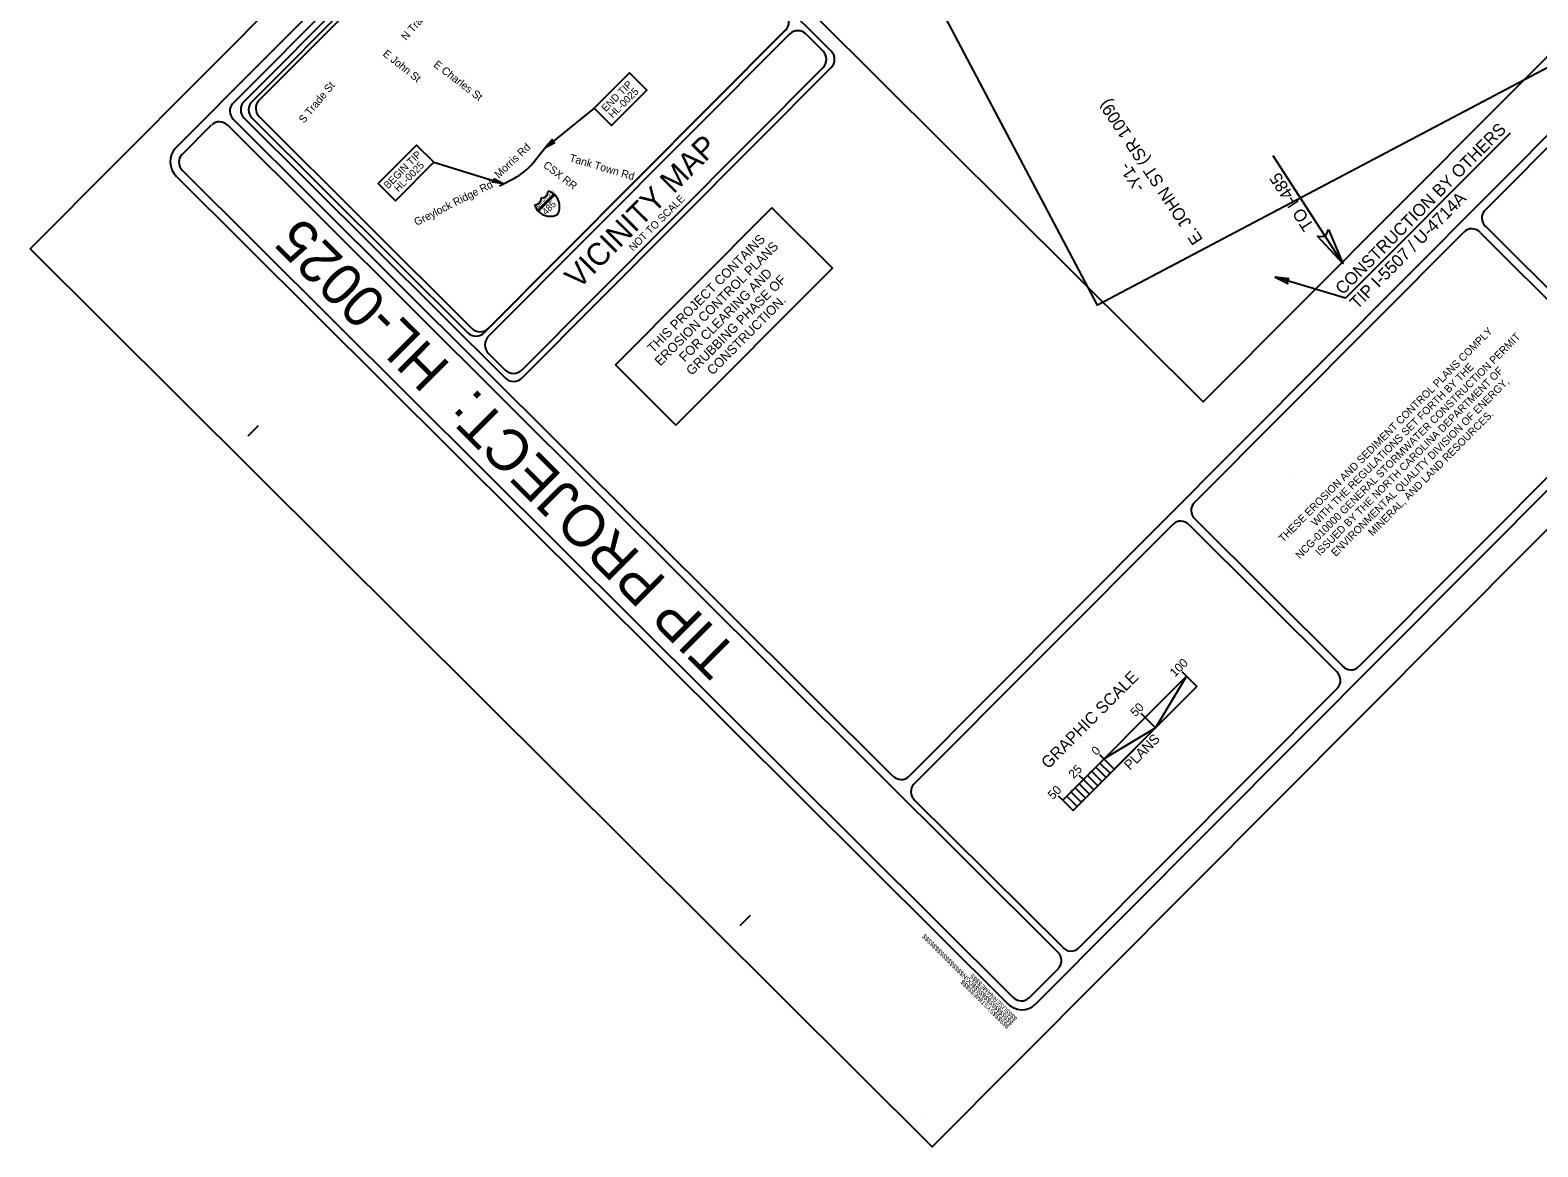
# Model space of a CAD drawing. Extents: x 1484932 to 1495672, y 495497 to 506262.
# Drawn here: x 1484932 to 1488841, y 495497 to 498393 of the extents above; entities that cross this region are included whole.
import ezdxf

# ---------------------------------------------------------------- set-up
doc = ezdxf.new("R2010")
doc.units = 0
for name, color, linetype in [('Default', 7, 'Continuous'), ('Old_Level_18', 7, 'Continuous'), ('Prop Dimension', 7, 'Continuous'), ('Prop DSN Text', 7, 'Continuous'), ('Prop DSN White Annotation Label', 7, 'Continuous'), ('Prop EOT', 7, 'Continuous'), ('Prop Grid Mask', 7, 'Continuous'), ('Prop Horizontal Alignment Station Label', 7, 'Continuous'), ('Prop Shade Light', 7, 'Continuous'), ('Prop Terminator CELL', 7, 'Continuous'), ('Scratch_Level_0', 7, 'Continuous'), ('Scratch_Level_4', 7, 'Continuous'), ('Sheet Plot Border Outside CELL', 7, 'Continuous'), ('Sheet Title CELL', 7, 'Continuous')]:
    doc.layers.add(name, color=color, linetype=linetype)

msp = doc.modelspace()

# ---------------------------------------------------------------- linework, layer by layer
at = {"layer": 'Old_Level_18'}
for p, q in [((1485457.2, 498202.7), (1488502.1, 501260.3)), ((1487209.6, 496457.5), (1490254.5, 499515.1)), ((1485486.3, 498207.8), (1486288.2, 499013)), ((1486331.1, 499013.1), (1487008.3, 498338.6)), ((1485507.1, 498207.8), (1486288.3, 498992.3)), ((1488703, 497925.4), (1489391.5, 498616.8)), ((1486890.2, 498392.8), (1486109, 497608.4)), ((1486900.5, 498382.5), (1486119.4, 497598.1)), ((1486943.4, 498382.6), (1486987.4, 498338.8)), ((1486987.5, 498295.9), (1486206.3, 497511.5)), ((1487008.4, 498295.8), (1486206.5, 497490.6)), ((1485325, 498070), (1485402.2, 498147.5)), ((1487596.2, 496002.1), (1485443.8, 498146.4)), ((1487168, 496458.6), (1485458.9, 498161.5)), ((1485486.4, 498165), (1486163.7, 497490.5)), ((1485507.2, 498165), (1486066.1, 497608.3)), ((1487479.8, 495885.3), (1485326.6, 498028.7)), ((1487949.3, 497166.9), (1488649.7, 497870.1)), ((1488690.9, 497868.6), (1489074.1, 497486.1)), ((1488704.7, 497884.2), (1489089.2, 497501.3)), ((1486119.4, 497555.2), (1486163.5, 497511.4)), ((1489075.4, 497444.6), (1488375.4, 496741.7)), ((1487950.9, 497125.6), (1488334.6, 496743.6)), ((1487222.9, 496437.6), (1487894.8, 497112.1)), ((1487936, 497110.7), (1488319.8, 496728.7)), ((1487929.3, 496718), (1487608.7, 496396)), ((1487929.3, 496718), (1487918.6, 496728.6)), ((1487956.2, 496691.2), (1487929.3, 496718)), ((1487635.6, 496369.3), (1487956.2, 496691.2)), ((1487649.7, 496012.7), (1488321.6, 496687.2)), ((1487822.5, 496610.6), (1487811.7, 496621.3)), ((1487822.5, 496610.6), (1487849.3, 496583.9)), ((1487715.6, 496503.3), (1487704.9, 496514)), ((1487662.2, 496449.7), (1487651.4, 496460.4)), ((1487683.5, 496471.1), (1487710.4, 496444.4)), ((1487609, 496014.7), (1487224.5, 496396.3)), ((1487608.7, 496396), (1487598, 496406.7)), ((1487598, 496406.7), (1487598, 496406.7)), ((1487608.7, 496396), (1487635.6, 496369.3)), ((1487608.7, 496396), (1487608.7, 496396)), ((1487521.5, 495883.4), (1487598.7, 495960.9))]:
    msp.add_line(p, q, dxfattribs=at)
for points in [[(1488483.8, 501275.3), (1485308.3, 498086.6)], [(1487537.4, 495866.7), (1490713.3, 499055.9)], [(1485311.2, 498013.2), (1487464.4, 495869.7)]]:
    msp.add_lwpolyline(points, dxfattribs=at)
for points in [[(1486448.9, 497525), (1486854.7, 497932.5), (1487011.7, 497776.1), (1486605.9, 497368.6)], [(1487929.3, 496718), (1487849.3, 496583.9), (1487956.2, 496691.2)], [(1487715.6, 496503.3), (1487849.3, 496583.9), (1487742.4, 496476.6)], [(1487672.8, 496460.4), (1487683.5, 496471.1), (1487710.4, 496444.4), (1487699.7, 496433.7)], [(1487694.2, 496481.9), (1487704.9, 496492.6), (1487731.7, 496465.9), (1487721.1, 496455.1)], [(1487630.1, 496417.5), (1487640.8, 496428.2), (1487667.6, 496401.5), (1487656.9, 496390.8)], [(1487651.5, 496438.9), (1487662.2, 496449.7), (1487689, 496422.9), (1487678.3, 496412.2)], [(1487608.7, 496396), (1487619.4, 496406.7), (1487646.2, 496380), (1487635.6, 496369.3)]]:
    msp.add_lwpolyline(points, close=True, dxfattribs=at)
for centre, start, end in [((1486868.7, 498414.2), 315.1186, 45.1186), ((1486922, 498361.1), 45.1186, 135.1186), ((1486966, 498317.3), 315.1186, 45.1186), ((1486986.9, 498317.2), 315.1186, 45.1186), ((1485507.8, 498186.4), 135.1186, 225.1186), ((1485528.5, 498186.5), 135.1186, 225.1186), ((1486087.5, 497629.8), 225.1186, 315.1186), ((1486140.8, 497576.7), 135.1186, 225.1186), ((1486184.8, 497532.9), 225.1186, 315.1186), ((1486185.1, 497512), 225.1185, 315.1186)]:
    msp.add_arc(centre, 30.3, start, end, dxfattribs=at)
for centre, major_axis, start_param, end_param in [((1485478.5, 498181.2), (-21.4, 21.3), 0, 1.570796), ((1485423.9, 498126.3), (-21.4, 21.3), 4.712389, 6.283185), ((1485346.7, 498048.8), (-38.2, 38), 0, 1.570796), ((1485346.7, 498048.8), (-21.4, 21.3), 0, 1.570796), ((1488724.3, 497903.9), (-21.4, 21.3), 6.282622, 7.852769), ((1488671.1, 497848.8), (-21.4, 21.3), 4.711278, 6.283185), ((1487970.7, 497145.5), (21.4, -21.3), 3.141593, 4.712389), ((1487916.2, 497090.8), (-21.4, 21.3), 4.712389, 6.283185), ((1488354.2, 496763.2), (21.4, -21.3), 4.712389, 6.283185), ((1488299.9, 496708.8), (21.4, -21.3), 0, 1.570796), ((1487188.1, 496478.7), (21.4, -21.3), 4.712389, 6.283185), ((1487244.4, 496416.3), (-21.4, 21.3), 0, 1.570796), ((1487576.7, 495982.4), (-21.4, 21.3), 3.141593, 4.712389), ((1487628.3, 496034.1), (21.4, -21.3), 4.712389, 6.283185), ((1487499.5, 495904.9), (21.4, -21.3), 4.712389, 6.283185), ((1487499.5, 495904.9), (38.2, -38), 4.712389, 6.283185)]:
    msp.add_ellipse(centre, major_axis=major_axis, ratio=0.927398, start_param=start_param, end_param=end_param, dxfattribs=at)
at = {"layer": 'Prop Dimension'}
for p, q in [((1488768.7, 498125.8), (1488342.2, 497697.5)), ((1488342.2, 497697.5), (1488159.7, 497752.5))]:
    msp.add_line(p, q, dxfattribs=at)
at = {"layer": 'Prop DSN Text'}
for p, q in [((1486394.3, 498190.6), (1486266.1, 498086.9)), ((1488335.3, 497788.1), (1488154.6, 498067.2)), ((1485978.1, 498050.3), (1486159.9, 497994.7))]:
    msp.add_line(p, q, dxfattribs=at)
at = {"layer": 'Prop DSN White Annotation Label'}
msp.add_lwpolyline([(1487208.7, 498608.1), (1488222.1, 499143.2), (1488965.4, 498493.7), (1489025.4, 498380), (1487698.9, 497679.6)], close=True, dxfattribs=at)
at = {"layer": 'Prop EOT'}
for p, q in [((1486447.6, 497997.8), (1486447.5, 497997.7)), ((1486447.6, 497997.8), (1486447.5, 497997.7)), ((1486447.5, 497997.7), (1486447.6, 497997.8)), ((1486289.3, 497967.6), (1486247.3, 497925.4)), ((1486247.4, 497925.5), (1486289.3, 497967.6)), ((1486291.7, 497965.5), (1486249.4, 497923.1)), ((1486249.4, 497923.1), (1486291.7, 497965.5))]:
    msp.add_line(p, q, dxfattribs=at)
for centre, radius, start, end in [((1486239.9, 497956.9), 16.8, 267.4184, 3.9692), ((1486257.7, 497974.8), 16.8, 266.268, 2.8189), ((1486262, 497935.1), 42.4, 49.933, 72.9434), ((1486262, 497935.1), 42.4, 45.6712, 49.9313), ((1486262, 497935.1), 42.4, 332.3215, 45.6591), ((1486279.6, 497952.8), 42.4, 197.294, 220.283), ((1486279.6, 497952.8), 42.4, 220.3043, 224.5656), ((1486279.6, 497952.8), 42.4, 224.5841, 297.9157)]:
    msp.add_arc(centre, radius, start, end, dxfattribs=at)
at = {"layer": 'Prop Grid Mask'}
for points in [[(1486394.3, 498190.6), (1486485.3, 498282), (1486530.2, 498237.2), (1486439.3, 498145.8)], [(1485833.9, 497995.1), (1485933.4, 498095), (1485978.4, 498050.2), (1485878.9, 497950.3)]]:
    msp.add_lwpolyline(points, close=True, dxfattribs=at)
at = {"layer": 'Prop Shade Light'}
for p, q in [((1486235.6, 498049.1), (1486274.8, 498097.7)), ((1486148.9, 497988.9), (1486187.2, 498009.2))]:
    msp.add_line(p, q, dxfattribs=at)
msp.add_arc((1486114.4, 498146.8), 155.7, 297.895, 321.1156, dxfattribs=at)
at = {"layer": 'Prop Terminator CELL'}
for points in [[(1486291.6, 498101.1), (1486266.1, 498086.9), (1486285.3, 498109.1), (1486285.7, 498102.8)], [(1486133.8, 498007.9), (1486159.9, 497994.7), (1486130.7, 497998.3), (1486135.7, 498002.1)], [(1488297.6, 497876.3), (1488335.3, 497788.1), (1488269.5, 497858.8), (1488290.2, 497857.8)], [(1488196, 497748), (1488159.7, 497752.5), (1488192.5, 497735.9), (1488190, 497743.4)]]:
    msp.add_lwpolyline(points, close=True, dxfattribs=at)
at = {"layer": 'Scratch_Level_4'}
for p, q in [((1485525.4, 498210.9), (1486049, 498736.6)), ((1486890.2, 498393.4), (1486119.3, 497619.4)), ((1485407.2, 498193.6), (1485407.2, 498193.6)), ((1485457.2, 498202.7), (1485457.2, 498202.7)), ((1486077.1, 497619.3), (1485525.5, 498168.6)), ((1485339.6, 498125.7), (1485339.6, 498125.7)), ((1488207.3, 497240.6), (1488207.3, 497240.6)), ((1487575.1, 495899.5), (1487575.1, 495899.5)), ((1487502.1, 495831.4), (1487502.1, 495831.4)), ((1487255, 495567.4), (1487255, 495567.4)), ((1487270, 495497.3), (1487270, 495497.3))]:
    msp.add_line(p, q, dxfattribs=at)
msp.add_lwpolyline([(1486969.7, 498427.7), (1489005, 500471.4), (1490008.1, 499472.4), (1487972.8, 497428.7)], close=True, dxfattribs=at)
for centre, start, end in [((1485546.6, 498189.8), 135.1181, 225.1181), ((1486098.1, 497640.5), 225.1181, 315.1182)]:
    msp.add_arc(centre, 29.9, start, end, dxfattribs=at)
msp.add_ellipse((1485346.7, 498048.8), major_axis=(-38.2, 38), ratio=0.927398, start_param=0, end_param=1.570796, dxfattribs=at)
at = {"layer": 'Sheet Plot Border Outside CELL'}
msp.add_lwpolyline([(1488496.6, 501405.6), (1484931.7, 497825.9), (1487270, 495497.3), (1490834.9, 499077)], close=True, dxfattribs=at)
at = {"layer": 'Sheet Title CELL'}
for p, q in [((1485497, 497341.3), (1485523.5, 497367.8)), ((1486772.4, 496071.1), (1486798.9, 496097.7))]:
    msp.add_line(p, q, dxfattribs=at)

# ---------------------------------------------------------------- texts
at = {"layer": 'Default'}
for s, rotation, p in [('N Trade St', 48.7859, (1485906.4, 498364.8)), ('E John St', 321.3901, (1485844.3, 498328.5)), ('E Charles St', 322.4571, (1485976, 498299.9)), ('S Trade St', 50.5492, (1485641.7, 498150.1)), ('Morris Rd', 43.598, (1486146.9, 498007.4)), ('Tank Town Rd', 343.3292, (1486328.3, 498053.3)), ('CSX RR', 322.4571, (1486260.1, 498039.2)), ('Greylock Ridge Rd', 26.8476, (1485933.3, 497885))]:
    msp.add_text(s, height=20, rotation=rotation, dxfattribs=at).set_placement(p)
at = {"layer": 'Old_Level_18'}
for s, height, rotation, p in [('TIP PROJECT:  HL-0025', 107.477, 135.1186, (1486772.1, 496780.1)), ('THIS PROJECT CONTAINS', 24.498, 45.1186, (1486546.6, 497554.7)), ('EROSION CONTROL PLANS', 24.498, 45.1186, (1486565.3, 497520.3)), ('FOR CLEARING AND', 24.498, 45.1186, (1486628.8, 497530.9)), ('GRUBBING PHASE OF', 24.498, 45.1186, (1486647.1, 497496)), ('CONSTRUCTION.', 24.498, 45.1186, (1486701.1, 497497)), ('THESE EROSION AND SEDIMENT CONTROL PLANS COMPLY', 19.7, 45.1186, (1488180.6, 497063.7)), ('NCG-010000 GENERAL STORMWATER CONSTRUCTION PERMIT ', 19.7, 45.1186, (1488223.8, 497020.4)), ('WITH THE REGULATIONS SET FORTH BY THE', 19.7, 45.1186, (1488265, 497105)), ('ISSUED BY THE NORTH CAROLINA DEPARTMENT OF ', 19.7, 45.1186, (1488275.3, 497028.7)), ('ENVIRONMENTAL QUALITY DIVISION OF ENERGY, ', 19.7, 45.1186, (1488316.5, 497026.7)), ('MINERAL, AND LAND RESOURCES.', 19.7, 45.1186, (1488412.4, 497079.6)), ('GRAPHIC SCALE', 30.851, 45.1186, (1487571.5, 496475.5)), ('100', 22.72, 45.1186, (1487899.8, 496714.1)), ('50', 22.72, 45.1186, (1487797.4, 496611.2)), ('PLANS', 25.75, 45.1186, (1487783.1, 496472.4)), ('0', 22.7, 45.1186, (1487696.5, 496510.6)), ('25', 22.72, 45.1186, (1487637.3, 496450.5)), ('50', 22.72, 45.1186, (1487583.6, 496396.6))]:
    msp.add_text(s, height=height, rotation=rotation, dxfattribs=at).set_placement(p)
at = {"layer": 'Prop DSN Text'}
for s, height, rotation, p in [('END TIP', 18.93, 45.1327, (1486424.2, 498179.8)), ('HL-0025', 18.93, 45.1327, (1486442.6, 498163.2)), ('CONSTRUCTION BY OTHERS', 32, 45.1191, (1488334.8, 497704.8)), ('BEGIN TIP', 18.93, 45.1327, (1485859.4, 497979.9)), ('HL-0025', 18.93, 45.1327, (1485886.5, 497971.9)), ('TO I-485', 32, 122.9223, (1488261.4, 497885.1)), ('TIP I-5507 / U-4714A', 32, 45.1191, (1488372.2, 497667.6))]:
    msp.add_text(s, height=height, rotation=rotation, dxfattribs=at).set_placement(p)
at = {"layer": 'Prop EOT'}
for s, height, p in [('INTERSTATE', 7.5, (1486248, 497928.2)), ('485', 17.47, (1486269.3, 497912.4))]:
    msp.add_text(s, height=height, rotation=45.1186, dxfattribs=at).set_placement(p)
at = {"layer": 'Prop Horizontal Alignment Station Label'}
for s, p in [('E. JOHN ST (SR 1009)', (1487973.4, 497849.9)), ('-Y1-', (1487824, 497986.4))]:
    msp.add_text(s, height=32, rotation=123.8699, dxfattribs=at).set_placement(p)
at = {"layer": 'Scratch_Level_0'}
for s, height, p in [('VICINITY MAP', 58.017, (1486353.3, 497719.2)), ('NOT TO SCALE', 19.542, (1486495.5, 497818.3))]:
    msp.add_text(s, height=height, rotation=45.1186, dxfattribs=at).set_placement(p)
at = {"layer": 'Scratch_Level_4'}
for s, p in [('$$$$$$$$$$$$$$$$DGN$$$$$$$$$$$$$$$$', (1487482.4, 495820.1)), ('$$$$$$SYSTIME$$$$$', (1487472.1, 495810.6)), ('$$$$USERNAME$$$$', (1487491.9, 495830.5))]:
    msp.add_text(s, height=11.782, rotation=135.1186, dxfattribs=at).set_placement(p)

doc.saveas('drawing.dxf')
